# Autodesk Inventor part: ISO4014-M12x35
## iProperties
Created: 2001-12
Part Number: ISO4014-M12x35
Document SubType Name: Modeling
Designer: Tobben
Control State: 0
Master: False
Checked Out: False
Shininess: 64.0
Length Units: 11269
Angle Units: 11279
Time Units: 11290
Mass Units: 11283
Length Display Precision: 3
Angle Display Precision: 2
Density: 0.0
Volumn: 0.0
Area: 0.0
PropertySet Name: Model Information
Author: Tobben
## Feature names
1. Base1
